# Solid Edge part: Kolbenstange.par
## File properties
Username: bmolnar
Dokumentum tartalom típus: 0
Author: bmolnar
Last saved by: bmolnar
Revision: 79
Sűrűség: 0,000 kg/m^3
Pontosság: 0,990
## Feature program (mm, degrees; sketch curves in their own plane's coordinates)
base feature "unnamed BaseFeature 1"
sketch for "unnamed Protrusion 1" plane through (0, 0, -16.4) normal (0, 0, -1) x-axis (0, 1, 0)
  circle centre (0, 0) radius 16
extrude "unnamed Protrusion 1" add finite 18.25 along +normal
sketch for "Kihúzás_2" #1 plane through (0, 0, -16.4) normal (0, 0, -1) x-axis (0, 1, 0)
  circle centre (0, 0) radius 6
sketch for "Kihúzás_2" #2 plane through (0, 0, -16.4) normal (0, 0, -1) x-axis (0, 1, 0)
  circle centre (0, 0) radius 16
extrude "Kihúzás_2" add finite 12.35 along -normal
sketch for "Furat_1" plane through (0, 0, 23.9) normal (0, 0, 1) x-axis (0, -1, 0)
  hole centre (0, 0) bore radius 2.4585
hole "Furat_1" nominal diameter 6 finite  VBottomAngle = 118 deg; ThreadDepth = 12.5 mm
chamfer "Letörés_1" setback 0.5  SetBackValue2 = 45 deg
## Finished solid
Body 1: solid body, 17 faces, 23 edges, 8 vertices.
  Faces by surface: plane 8, cylinder 5, cone 3, torus 1
  Edges by curve: circle 13, line 6, curve on surface 2, ellipse 2
Bounding box of the edges (mm; curved faces can reach further): 32.000 x 32.000 x 61.050, from (-16, -16, -34.65) to (16, 16, 26.4).
Cylindrical faces by radius (mm): R2.4585 x2, R3.125 x1, R6 x1, R16 x1
Conical faces (half-angle, radius in mm at the cone's reference point): 45 deg R2.9585 x1, 45 deg R3.225 x1, 59 deg R2.4585 x1
Toroidal faces (ring radius, tube radius in mm): R4.7 r1.3 x1
Planar faces by outward normal: +x 1, +z 3, -x 1, -z 1, oblique 2
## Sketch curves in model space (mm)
circle centre (0, 0, -16.4) radius 16
circle centre (0, 0, -16.4) radius 6
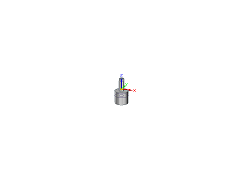
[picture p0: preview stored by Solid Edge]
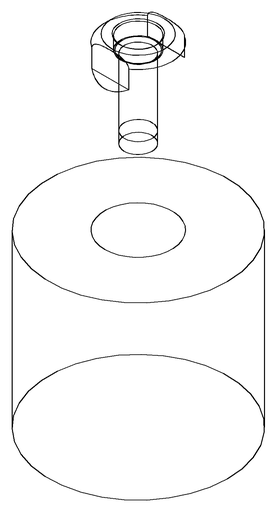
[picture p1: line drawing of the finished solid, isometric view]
